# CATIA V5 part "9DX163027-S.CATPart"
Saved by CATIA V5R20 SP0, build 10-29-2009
Part number: 9DX163027-S
Revision: ANY
Definition: UNKNOWN
Nomenclature: 9DX163027-S
Source: Unknown
Bounding box of the stored display mesh (mm): x -3.5 to 3.5, y -3.181 to 2.412, z -2.5 to 2.5
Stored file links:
  C:\Users\Utente\Desktop\IO LAVORO\3D X SITO CF\CUMSA\3D files DX\DX 163027\9DX163027-S.CATPart
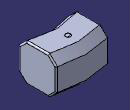
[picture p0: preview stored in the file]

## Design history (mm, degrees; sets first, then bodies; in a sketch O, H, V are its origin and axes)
Body1 "Diámetro de taladro Ø0.7 (0.7)1" (main body)
  Solid1: solid without history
